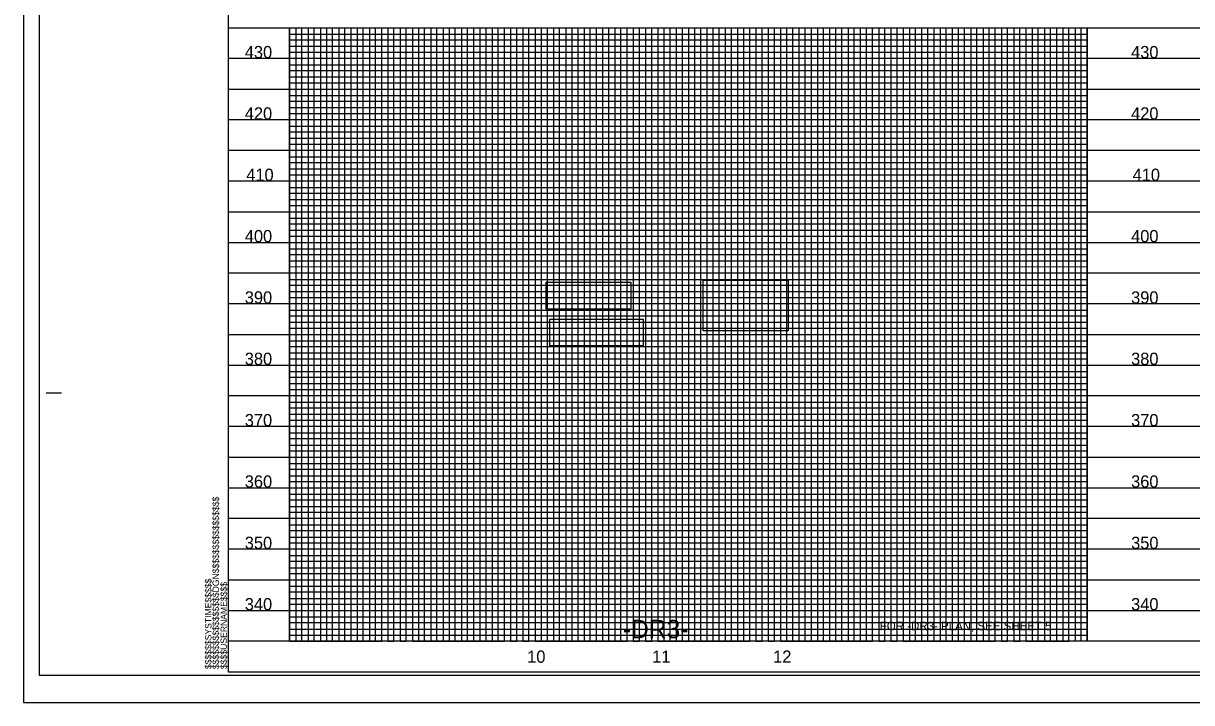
# Model space of a CAD drawing. Extents: x 1629787 to 1631995, y 1166253 to 1167353.
# Drawn here: x 1629787 to 1630739, y 1166253 to 1166807 of the extents above; entities that cross this region are included whole.
import ezdxf

# ---------------------------------------------------------------- set-up
doc = ezdxf.new("R2010")
doc.units = 0
for name, color, linetype in [('Exist Vertical Profile Horizontal Axis Label Major', 7, 'Continuous'), ('Exist Vertical Profile Vertical Axis Label', 7, 'Continuous'), ('Prop Grid Mask', 7, 'Continuous'), ('Sheet Data Field CELL', 7, 'Continuous'), ('Sheet Layout Profile Border Port 1', 7, 'Continuous'), ('Sheet Plan CELL', 7, 'Continuous'), ('Sheet Plot Border Inside CELL', 7, 'Continuous'), ('Sheet Plot Border Outside CELL', 7, 'Continuous'), ('Sheet Profile CELL', 7, 'Continuous'), ('Sheet Profile Grid Major CELL', 7, 'Continuous'), ('Sheet Profile Grid Middle CELL', 7, 'Continuous'), ('Sheet Profile Grid Minor CELL', 7, 'Continuous')]:
    doc.layers.add(name, color=color, linetype=linetype)

msp = doc.modelspace()

# ---------------------------------------------------------------- linework, layer by layer
at = {"layer": 'Prop Grid Mask'}
for points in [[(1630213.25, 1166596.07), (1630282.32, 1166596.07), (1630282.32, 1166574.1), (1630213.25, 1166574.1)], [(1630341.33, 1166597.69), (1630410.4, 1166597.69), (1630410.4, 1166556.52), (1630341.33, 1166556.52)], [(1630216.23, 1166565.98), (1630292.32, 1166565.98), (1630292.32, 1166544.27), (1630216.23, 1166544.27)], [(1630454.31, 1166328.4), (1630654.31, 1166328.4), (1630654.31, 1166303.4), (1630454.31, 1166303.4)], [(1630224.31, 1166323.4), (1630384.31, 1166323.4), (1630384.31, 1166303.4), (1630224.31, 1166303.4)]]:
    msp.add_lwpolyline(points, close=True, dxfattribs=at)
at = {"layer": 'Sheet Layout Profile Border Port 1'}
msp.add_lwpolyline([(1630004.31, 1166803.4), (1630654.31, 1166803.4), (1630654.31, 1166303.4), (1630004.31, 1166303.4)], close=True, dxfattribs=at)
at = {"layer": 'Sheet Plot Border Inside CELL'}
msp.add_lwpolyline([(1629800.31, 1166275.85), (1631466.81, 1166275.85), (1631466.81, 1167330.95), (1629800.31, 1167330.95)], close=True, dxfattribs=at)
at = {"layer": 'Sheet Plot Border Outside CELL'}
msp.add_lwpolyline([(1629787.31, 1166253.4), (1631471.31, 1166253.4), (1631471.31, 1167353.4), (1629787.31, 1167353.4)], close=True, dxfattribs=at)
at = {"layer": 'Sheet Profile CELL'}
for p, q in [((1629954.31, 1166803.4), (1631454.31, 1166803.4)), ((1629805.81, 1166505.9), (1629818.31, 1166505.9)), ((1631454.31, 1166303.4), (1629954.31, 1166303.4)), ((1629954.31, 1166278.4), (1631454.31, 1166278.4)), ((1629954.31, 1166278.4), (1629954.31, 1166278.4)), ((1629954.31, 1166278.4), (1629954.31, 1166278.4)), ((1629954.31, 1166278.4), (1629954.31, 1166278.4)), ((1629954.31, 1166278.4), (1629954.31, 1166278.4)), ((1629954.31, 1166278.4), (1629954.31, 1166278.4)), ((1629954.31, 1166278.4), (1629954.31, 1166278.4)), ((1629954.31, 1166278.4), (1629954.31, 1166278.4))]:
    msp.add_line(p, q, dxfattribs=at)
msp.add_lwpolyline([(1631454.31, 1167328.4), (1629954.31, 1167328.4), (1629954.31, 1166278.4), (1631454.31, 1166278.4)], close=True, dxfattribs=at)
msp.add_lwpolyline([(1629991.81, 1166278.4), (1629991.81, 1166278.4)], dxfattribs=at)
at = {"layer": 'Sheet Profile Grid Major CELL'}
for p, q in [((1630004.31, 1166803.4), (1630004.31, 1166303.4)), ((1630054.31, 1166303.4), (1630054.31, 1166803.4)), ((1630054.31, 1166803.4), (1630104.31, 1166803.4)), ((1630104.31, 1166803.4), (1630104.31, 1166303.4)), ((1630154.31, 1166303.4), (1630154.31, 1166803.4)), ((1630154.31, 1166803.4), (1630204.31, 1166803.4)), ((1630204.31, 1166803.4), (1630204.31, 1166303.4)), ((1630254.31, 1166303.4), (1630254.31, 1166803.4)), ((1630254.31, 1166803.4), (1630304.31, 1166803.4)), ((1630304.31, 1166803.4), (1630304.31, 1166303.4)), ((1630354.31, 1166303.4), (1630354.31, 1166803.4)), ((1630354.31, 1166803.4), (1630404.31, 1166803.4)), ((1630404.31, 1166803.4), (1630404.31, 1166303.4)), ((1630454.31, 1166803.4), (1630504.31, 1166803.4)), ((1630454.31, 1166303.4), (1630454.31, 1166803.4)), ((1630454.31, 1166803.4), (1630504.31, 1166803.4)), ((1630504.31, 1166803.4), (1630504.31, 1166303.4)), ((1630554.31, 1166803.4), (1630604.31, 1166803.4)), ((1630554.31, 1166303.4), (1630554.31, 1166803.4)), ((1630554.31, 1166803.4), (1630604.31, 1166803.4)), ((1630604.31, 1166803.4), (1630604.31, 1166303.4)), ((1630654.31, 1166803.4), (1630704.31, 1166803.4)), ((1630654.31, 1166303.4), (1630654.31, 1166803.4)), ((1630654.31, 1166803.4), (1630704.31, 1166803.4)), ((1629954.31, 1166303.4), (1629954.31, 1166303.4)), ((1630004.31, 1166303.4), (1630054.31, 1166303.4)), ((1630104.31, 1166303.4), (1630154.31, 1166303.4)), ((1630204.31, 1166303.4), (1630254.31, 1166303.4)), ((1630304.31, 1166303.4), (1630354.31, 1166303.4)), ((1630404.31, 1166303.4), (1630454.31, 1166303.4)), ((1630504.31, 1166303.4), (1630554.31, 1166303.4)), ((1630604.31, 1166303.4), (1630634.31, 1166303.4))]:
    msp.add_line(p, q, dxfattribs=at)
for points in [[(1631454.31, 1166778.4), (1629954.31, 1166778.4)], [(1631454.31, 1166728.4), (1629954.31, 1166728.4)], [(1631454.31, 1166678.4), (1629954.31, 1166678.4), (1629954.31, 1166628.4), (1631454.31, 1166628.4)], [(1631454.31, 1166578.4), (1629954.31, 1166578.4), (1629954.31, 1166528.4), (1631454.31, 1166528.4)], [(1631454.31, 1166478.4), (1629954.31, 1166478.4), (1629954.31, 1166428.4), (1631454.31, 1166428.4)], [(1631454.31, 1166378.4), (1629954.31, 1166378.4), (1629954.31, 1166378.4), (1629954.31, 1166328.4), (1631454.31, 1166328.4)], [(1631454.31, 1166303.4), (1629954.31, 1166303.4)]]:
    msp.add_lwpolyline(points, dxfattribs=at)
at = {"layer": 'Sheet Profile Grid Middle CELL'}
msp.add_line((1630679.31, 1166803.4), (1630729.31, 1166803.4), dxfattribs=at)
for points in [[(1629979.31, 1166803.4), (1630029.31, 1166803.4), (1630029.31, 1166303.4), (1630079.31, 1166303.4), (1630079.31, 1166803.4), (1630129.31, 1166803.4), (1630129.31, 1166303.4), (1630179.31, 1166303.4), (1630179.31, 1166803.4), (1630229.31, 1166803.4), (1630229.31, 1166303.4), (1630279.31, 1166303.4), (1630279.31, 1166803.4), (1630329.31, 1166803.4), (1630329.31, 1166303.4), (1630379.31, 1166303.4), (1630379.31, 1166803.4), (1630429.31, 1166803.4), (1630429.31, 1166303.4), (1630479.31, 1166303.4), (1630479.31, 1166803.4), (1630529.31, 1166803.4), (1630529.31, 1166303.4), (1630579.31, 1166303.4), (1630579.31, 1166303.4), (1630579.31, 1166803.4), (1630629.31, 1166803.4), (1630629.31, 1166303.4)], [(1629954.31, 1166753.4), (1631454.31, 1166753.4)], [(1631454.31, 1166703.4), (1629954.31, 1166703.4), (1629954.31, 1166653.4), (1631454.31, 1166653.4)], [(1631454.31, 1166603.4), (1629954.31, 1166603.4), (1629954.31, 1166553.4), (1631454.31, 1166553.4)], [(1631454.31, 1166503.4), (1629954.31, 1166503.4), (1629954.31, 1166453.4), (1631454.31, 1166453.4)], [(1631454.31, 1166403.4), (1629954.31, 1166403.4), (1629954.31, 1166353.4), (1631454.31, 1166353.4)], [(1631454.31, 1166303.4), (1629954.31, 1166303.4)]]:
    msp.add_lwpolyline(points, dxfattribs=at)
at = {"layer": 'Sheet Profile Grid Minor CELL'}
for p, q in [((1630534.31, 1166803.4), (1630534.31, 1166303.4)), ((1630539.31, 1166303.4), (1630539.31, 1166803.4)), ((1630539.31, 1166803.4), (1630544.31, 1166803.4)), ((1630544.31, 1166803.4), (1630544.31, 1166303.4)), ((1630549.31, 1166303.4), (1630549.31, 1166803.4)), ((1630549.31, 1166803.4), (1630559.31, 1166803.4)), ((1630559.31, 1166803.4), (1630559.31, 1166303.4)), ((1630564.31, 1166303.4), (1630564.31, 1166803.4)), ((1630564.31, 1166803.4), (1630569.31, 1166803.4)), ((1630569.31, 1166803.4), (1630569.31, 1166303.4)), ((1630574.31, 1166303.4), (1630574.31, 1166803.4)), ((1630574.31, 1166803.4), (1630584.31, 1166803.4)), ((1630584.31, 1166803.4), (1630584.31, 1166303.4)), ((1630589.31, 1166303.4), (1630589.31, 1166803.4)), ((1630589.31, 1166803.4), (1630594.31, 1166803.4)), ((1630594.31, 1166803.4), (1630594.31, 1166303.4)), ((1630599.31, 1166303.4), (1630599.31, 1166803.4)), ((1630599.31, 1166803.4), (1630609.31, 1166803.4)), ((1630609.31, 1166803.4), (1630609.31, 1166303.4)), ((1630614.31, 1166303.4), (1630614.31, 1166803.4)), ((1630614.31, 1166803.4), (1630619.31, 1166803.4)), ((1630619.31, 1166803.4), (1630619.31, 1166303.4)), ((1630624.31, 1166303.4), (1630624.31, 1166803.4)), ((1630624.31, 1166803.4), (1630634.31, 1166803.4)), ((1630634.31, 1166803.4), (1630634.31, 1166303.4)), ((1630639.31, 1166303.4), (1630639.31, 1166803.4)), ((1630639.31, 1166803.4), (1630644.31, 1166803.4)), ((1630644.31, 1166803.4), (1630644.31, 1166303.4)), ((1630649.31, 1166303.4), (1630649.31, 1166803.4)), ((1630649.31, 1166803.4), (1630659.31, 1166803.4)), ((1630664.31, 1166803.4), (1630669.31, 1166803.4)), ((1630674.31, 1166803.4), (1630684.31, 1166803.4)), ((1630004.31, 1166798.4), (1630654.31, 1166798.4)), ((1630654.31, 1166793.4), (1630004.31, 1166793.4)), ((1630004.31, 1166788.4), (1630654.31, 1166788.4)), ((1630654.31, 1166783.4), (1630004.31, 1166783.4)), ((1630004.31, 1166773.4), (1630654.31, 1166773.4)), ((1630654.31, 1166768.4), (1630004.31, 1166768.4)), ((1630004.31, 1166763.4), (1630654.31, 1166763.4)), ((1630654.31, 1166758.4), (1630004.31, 1166758.4)), ((1630004.31, 1166748.4), (1630654.31, 1166748.4)), ((1630654.31, 1166743.4), (1630004.31, 1166743.4)), ((1630004.31, 1166738.4), (1630654.31, 1166738.4)), ((1630654.31, 1166733.4), (1630004.31, 1166733.4)), ((1630004.31, 1166723.4), (1630654.31, 1166723.4)), ((1630654.31, 1166718.4), (1630004.31, 1166718.4)), ((1630004.31, 1166713.4), (1630654.31, 1166713.4)), ((1630654.31, 1166708.4), (1630004.31, 1166708.4)), ((1630004.31, 1166698.4), (1630654.31, 1166698.4)), ((1630654.31, 1166693.4), (1630004.31, 1166693.4)), ((1630004.31, 1166688.4), (1630654.31, 1166688.4)), ((1630654.31, 1166683.4), (1630004.31, 1166683.4)), ((1630004.31, 1166673.4), (1630654.31, 1166673.4)), ((1630654.31, 1166668.4), (1630004.31, 1166668.4)), ((1630004.31, 1166663.4), (1630654.31, 1166663.4)), ((1630654.31, 1166658.4), (1630004.31, 1166658.4)), ((1630004.31, 1166648.4), (1630654.31, 1166648.4)), ((1630654.31, 1166643.4), (1630004.31, 1166643.4)), ((1630004.31, 1166638.4), (1630654.31, 1166638.4)), ((1630654.31, 1166633.4), (1630004.31, 1166633.4)), ((1630004.31, 1166623.4), (1630654.31, 1166623.4)), ((1630654.31, 1166618.4), (1630004.31, 1166618.4)), ((1630004.31, 1166613.4), (1630654.31, 1166613.4)), ((1630654.31, 1166608.48), (1630004.31, 1166608.55)), ((1630004.31, 1166598.4), (1630654.31, 1166598.4)), ((1630654.31, 1166593.4), (1630004.31, 1166593.4)), ((1630004.31, 1166588.4), (1630654.31, 1166588.4)), ((1630654.31, 1166583.4), (1630004.31, 1166583.4)), ((1630004.31, 1166573.4), (1630654.31, 1166573.4)), ((1630654.31, 1166568.4), (1630004.31, 1166568.4)), ((1630004.31, 1166563.4), (1630654.31, 1166563.4)), ((1630654.31, 1166558.4), (1630004.31, 1166558.4)), ((1630004.31, 1166548.4), (1630654.31, 1166548.4)), ((1630654.31, 1166543.4), (1630004.31, 1166543.4)), ((1630004.31, 1166538.4), (1630654.31, 1166538.4)), ((1630654.31, 1166533.4), (1630004.31, 1166533.4)), ((1630004.31, 1166523.4), (1630654.31, 1166523.4)), ((1630654.31, 1166518.4), (1630004.31, 1166518.4)), ((1630004.31, 1166513.4), (1630654.31, 1166513.4)), ((1630654.31, 1166508.4), (1630004.31, 1166508.4)), ((1630004.31, 1166498.4), (1630654.31, 1166498.4)), ((1630654.31, 1166493.4), (1630004.31, 1166493.4)), ((1630004.31, 1166488.4), (1630654.31, 1166488.4)), ((1630654.31, 1166483.4), (1630004.31, 1166483.4)), ((1630004.31, 1166473.4), (1630654.31, 1166473.4)), ((1630654.31, 1166468.4), (1630004.31, 1166468.4)), ((1630004.31, 1166463.4), (1630654.31, 1166463.4)), ((1630654.31, 1166458.4), (1630004.31, 1166458.4)), ((1630004.31, 1166448.4), (1630654.31, 1166448.4)), ((1630654.31, 1166443.4), (1630004.31, 1166443.4)), ((1630004.31, 1166438.4), (1630654.31, 1166438.4)), ((1630654.31, 1166433.4), (1630004.31, 1166433.4)), ((1630004.31, 1166423.4), (1630654.31, 1166423.4)), ((1630654.31, 1166418.4), (1630004.31, 1166418.4)), ((1630004.31, 1166413.4), (1630654.31, 1166413.4)), ((1630654.31, 1166408.4), (1630004.31, 1166408.4)), ((1630004.31, 1166398.4), (1630654.31, 1166398.4)), ((1630654.31, 1166393.4), (1630004.31, 1166393.4)), ((1630004.31, 1166388.4), (1630654.31, 1166388.4)), ((1630654.31, 1166383.4), (1630004.31, 1166383.4)), ((1630004.31, 1166373.4), (1630654.31, 1166373.4)), ((1630654.31, 1166368.4), (1630004.31, 1166368.4)), ((1630004.31, 1166363.4), (1630654.31, 1166363.4)), ((1630654.31, 1166358.4), (1630004.31, 1166358.4)), ((1630004.31, 1166348.4), (1630654.31, 1166348.4)), ((1630654.31, 1166343.4), (1630004.31, 1166343.4)), ((1630004.31, 1166338.4), (1630654.31, 1166338.4)), ((1630654.31, 1166333.4), (1630004.31, 1166333.4)), ((1630004.31, 1166323.4), (1630654.31, 1166323.4)), ((1630654.31, 1166318.4), (1630004.31, 1166318.4)), ((1630004.31, 1166313.4), (1630654.31, 1166313.4)), ((1630004.31, 1166308.4), (1630654.31, 1166308.4)), ((1630534.31, 1166303.4), (1630539.31, 1166303.4)), ((1630544.31, 1166303.4), (1630549.31, 1166303.4)), ((1630559.31, 1166303.4), (1630564.31, 1166303.4)), ((1630569.31, 1166303.4), (1630574.31, 1166303.4)), ((1630584.31, 1166303.4), (1630589.31, 1166303.4)), ((1630594.31, 1166303.4), (1630599.31, 1166303.4)), ((1630609.31, 1166303.4), (1630614.31, 1166303.4)), ((1630619.31, 1166303.4), (1630624.31, 1166303.4)), ((1630634.31, 1166303.4), (1630639.31, 1166303.4))]:
    msp.add_line(p, q, dxfattribs=at)
for points in [[(1630004.31, 1166803.4), (1630009.31, 1166803.4), (1630009.31, 1166303.4), (1630014.31, 1166303.4), (1630014.31, 1166803.4), (1630019.31, 1166803.4), (1630019.31, 1166303.4), (1630024.31, 1166303.4), (1630024.31, 1166803.4), (1630034.31, 1166803.4), (1630034.31, 1166303.4), (1630039.31, 1166303.4), (1630039.31, 1166803.4), (1630044.31, 1166803.4), (1630044.31, 1166303.4), (1630049.31, 1166303.4), (1630059.31, 1166303.4), (1630064.31, 1166303.4), (1630064.31, 1166803.4), (1630069.31, 1166803.4), (1630069.31, 1166303.4), (1630074.31, 1166303.4), (1630074.31, 1166803.4), (1630084.31, 1166803.4), (1630084.31, 1166303.4), (1630089.31, 1166303.4), (1630089.31, 1166803.4), (1630094.31, 1166803.4), (1630094.31, 1166303.4), (1630099.31, 1166303.4), (1630099.31, 1166803.4), (1630109.31, 1166803.4), (1630109.31, 1166303.4), (1630114.31, 1166303.4), (1630114.31, 1166803.4), (1630119.31, 1166803.4), (1630119.31, 1166303.4), (1630124.31, 1166303.4), (1630124.31, 1166803.4), (1630134.31, 1166803.4), (1630134.31, 1166303.4), (1630139.31, 1166303.4), (1630139.31, 1166803.4), (1630144.31, 1166803.4), (1630144.31, 1166303.4), (1630149.31, 1166303.4), (1630149.31, 1166803.4), (1630159.31, 1166803.4), (1630159.31, 1166303.4), (1630164.31, 1166303.4), (1630164.31, 1166803.4), (1630169.31, 1166803.4), (1630169.31, 1166303.4), (1630174.31, 1166303.4), (1630174.31, 1166803.4), (1630184.31, 1166803.4), (1630184.31, 1166303.4), (1630189.31, 1166303.4), (1630189.31, 1166803.4), (1630194.31, 1166803.4), (1630194.31, 1166303.4), (1630199.31, 1166303.4), (1630199.31, 1166803.4), (1630209.31, 1166803.4), (1630209.31, 1166303.4), (1630214.31, 1166303.4), (1630214.31, 1166803.4), (1630219.31, 1166803.4), (1630219.31, 1166303.4)], [(1630049.31, 1166303.4), (1630049.31, 1166803.4), (1630059.31, 1166803.4), (1630059.31, 1166303.4)], [(1630219.31, 1166303.4), (1630224.31, 1166303.4), (1630224.31, 1166803.4), (1630234.31, 1166803.4), (1630234.31, 1166303.4), (1630239.31, 1166303.4), (1630239.31, 1166803.4), (1630244.31, 1166803.4), (1630244.31, 1166303.4), (1630249.31, 1166303.4), (1630249.31, 1166803.4), (1630259.31, 1166803.4), (1630259.31, 1166303.4), (1630264.31, 1166303.4), (1630264.31, 1166803.4), (1630269.31, 1166803.4), (1630269.31, 1166303.4), (1630274.31, 1166303.4), (1630274.31, 1166803.4), (1630284.31, 1166803.4), (1630284.31, 1166303.4), (1630289.31, 1166303.4), (1630289.31, 1166803.4), (1630294.31, 1166803.4), (1630294.31, 1166303.4), (1630299.31, 1166303.4), (1630299.31, 1166803.4), (1630309.31, 1166803.4), (1630309.31, 1166303.4), (1630314.31, 1166303.4), (1630314.31, 1166803.4), (1630319.31, 1166803.4), (1630319.31, 1166303.4), (1630324.31, 1166303.4), (1630324.31, 1166803.4), (1630334.31, 1166803.4), (1630334.31, 1166303.4), (1630339.31, 1166303.4), (1630339.31, 1166803.4), (1630344.31, 1166803.4), (1630344.31, 1166303.4), (1630349.31, 1166303.4), (1630349.31, 1166803.4), (1630359.31, 1166803.4), (1630359.31, 1166303.4), (1630364.31, 1166303.4), (1630364.31, 1166803.4), (1630369.31, 1166803.4), (1630369.31, 1166303.4), (1630374.31, 1166303.4), (1630374.31, 1166803.4), (1630384.31, 1166803.4), (1630384.31, 1166303.4), (1630389.31, 1166303.4), (1630389.31, 1166803.4), (1630394.31, 1166803.4), (1630394.31, 1166303.4), (1630399.31, 1166303.4), (1630399.31, 1166803.4), (1630409.31, 1166803.4), (1630409.31, 1166303.4), (1630414.31, 1166303.4), (1630414.31, 1166803.4), (1630419.31, 1166803.4), (1630419.31, 1166303.4), (1630424.31, 1166303.4), (1630424.31, 1166803.4), (1630434.31, 1166803.4), (1630434.31, 1166303.4), (1630439.31, 1166303.4), (1630439.31, 1166803.4), (1630444.31, 1166803.4), (1630444.31, 1166303.4), (1630449.31, 1166303.4), (1630449.31, 1166803.4), (1630459.31, 1166803.4), (1630459.31, 1166303.4), (1630464.31, 1166303.4), (1630464.31, 1166803.4), (1630469.31, 1166803.4), (1630469.31, 1166303.4), (1630474.31, 1166303.4), (1630474.31, 1166803.4), (1630484.31, 1166803.4), (1630484.31, 1166303.4), (1630489.31, 1166303.4), (1630489.31, 1166803.4), (1630494.31, 1166803.4), (1630494.31, 1166303.4), (1630499.31, 1166303.4), (1630499.31, 1166803.4), (1630509.31, 1166803.4), (1630509.31, 1166303.4), (1630514.31, 1166303.4), (1630514.31, 1166803.4), (1630519.31, 1166803.4), (1630519.31, 1166303.4), (1630524.31, 1166303.4), (1630524.31, 1166803.4), (1630534.31, 1166803.4)]]:
    msp.add_lwpolyline(points, dxfattribs=at)

# ---------------------------------------------------------------- texts
at = {"layer": 'Exist Vertical Profile Horizontal Axis Label Major'}
for s, p in [('10', (1630197.9, 1166285.9)), ('11', (1630299.74, 1166285.9)), ('12', (1630398.29, 1166285.9))]:
    msp.add_text(s, height=10, dxfattribs=at).set_placement(p)
at = {"layer": 'Exist Vertical Profile Vertical Axis Label'}
for s, p in [('430', (1629967.75, 1166778.65)), ('430', (1630690, 1166778.65)), ('420', (1629967.75, 1166728.65)), ('420', (1630690, 1166728.65)), ('410', (1629968.94, 1166678.65)), ('410', (1630691.2, 1166678.65)), ('400', (1629967.75, 1166628.65)), ('400', (1630690, 1166628.65)), ('390', (1629967.75, 1166578.65)), ('390', (1630690, 1166578.65)), ('380', (1629967.75, 1166528.65)), ('380', (1630690, 1166528.65)), ('370', (1629967.75, 1166478.65)), ('370', (1630690, 1166478.65)), ('360', (1629967.75, 1166428.65)), ('360', (1630690, 1166428.65)), ('350', (1629967.75, 1166378.65)), ('350', (1630690, 1166378.65)), ('340', (1629967.75, 1166328.65)), ('340', (1630690, 1166328.65))]:
    msp.add_text(s, height=10, dxfattribs=at).set_placement(p)
at = {"layer": 'Sheet Data Field CELL'}
for s, height, p in [('-DR3-', 15, (1630275.8, 1166305.9)), ('FOR -DR3- PLAN, SEE SHEET 5', 7, (1630485.19, 1166312.4))]:
    msp.add_text(s, height=height, rotation=360, dxfattribs=at).set_placement(p)
at = {"layer": 'Sheet Plan CELL'}
for s, p in [('$$$$$$$$$$$$$$$$DGN$$$$$$$$$$$$$$$$', (1629946.68, 1166280.76)), ('$$$$$$SYSTIME$$$$$', (1629940.6, 1166280.74)), ('$$$$USERNAME$$$$', (1629953.23, 1166280.78))]:
    msp.add_text(s, height=5.25, rotation=90, dxfattribs=at).set_placement(p)

doc.saveas('drawing.dxf')
